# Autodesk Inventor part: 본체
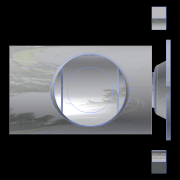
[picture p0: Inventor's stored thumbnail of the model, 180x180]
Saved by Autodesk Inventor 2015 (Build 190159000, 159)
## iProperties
Created: 2017-10
Part Number: 본체
Material: 알루미늄 6061
Document SubType Name: Modeling
Designer: Administrator
Density: 2.7 g/cm^3
Appearance: 알루미늄 - 평지
Mass: 787.092 g
Surface Area: 684.645 cm^2
Volume: 291.516 cm^3
Author: Administrator
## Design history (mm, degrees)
sketch "스케치2"
  geometry: C1 r 31 at (0, 0); 1 further point
  constraints: 1 centre point, 1 coincident
  dimensions: "d1" = 62 diameter of C1
extrude "돌출1" new body sketch "스케치2" stored distance "d2" = 112; taper "d3" = 0 deg
node "작업 평면5"
sketch "스케치5"
  geometry: 1 further point
hole "구멍1" sketch "스케치5" at (0, 0) diameter "d12" = 40.376; stored, may be unused: countersink angle "d16" = 90 deg, drill point angle "d18" = 0 deg; dims "d13" = 84, "d14" = 4, "d15" = 2, "d17" = 9
sketch "스케치6"
  geometry: L1 (20.188, 47)-(-20.188, 47) reference; L2 (31, -56)-(31, 56) reference; L3 (-31, -56)-(-31, 56) reference; L4 (31, 56)-(-31, 56) reference; L5 (20.188, 47)-(24, 47); L6 (24, 47)-(24, 44); L7 (24, 44)-(20, 44); L8 (20, 44)-(20, 35); L9 (20, 35)-(17.5, 35); L10 (17.5, 35)-(17.5, 31.7); L11 (17.5, 31.7)-(18.5, 31.7); L12 (18.5, 31.7)-(18.5, 30); L13 (18.5, 30)-(17.5, 30); L14 (17.5, 30)-(17.5, 19); L15 (17.5, 19)-(26, 19); L16 (26, 19)-(20, 19); L17 (0, 0)-(0, 56); L18 (26, 19)-(26, -19); L19 (26, -19)-(17.5, -19); L20 (17.5, -19)-(17.5, -30); L21 (17.5, -30)-(16.5, -30); L22 (16.5, -30)-(16.5, -35); L23 (16.5, -35)-(10, -35); L24 (10, -35)-(10, -37.7); L25 (10, -37.7)-(12.5, -37.7); L26 (12.5, -37.7)-(12.5, -45); L27 (12.5, -45)-(16.5, -45); L28 (16.5, -45)-(22, -56); L29 (0, 0)-(0, -56); L30 (22, -56)-(0, -56); L31 (20.188, 47)-(0, 47); L32 (-31, -56)-(31, -56) reference
  constraints: 54 end point, 16 perpendicular, 4 horizontal, 4 point on line, 2 midpoint, 2 vertical, 1 horizontal alignment
  dimensions: "d19" = 48 diameter of L6 L17; "d20" = 3 distance between parallel lines of L7 L5; "d21" = 9 distance between parallel lines of L9 L7; "d22" = 40 diameter of L8 L17; "d23" = 35 diameter of L10 L17; "d24" = 26 distance between parallel lines of L13 L4; "d25" = 37 diameter of L12 L17; "d26" = 1.7 distance between parallel lines of L13 L11; "d27" = 11 distance between parallel lines of L15 L13; "d29" = 52 diameter of L18 L17; "d30" = 38 distance of L15.end L18.end; "d31" = 11 distance between parallel lines of L21 L19; "d32" = 35 diameter of L20 L17; "d33" = 5 distance between parallel lines of L23 L21; "d34" = 33 diameter of L22 L17; "d35" = 20 diameter of L24 L17; "d36" = 2.7 distance between parallel lines of L23 L25; "d37" = 7.3 distance between parallel lines of L27 L25; "d38" = 25 diameter of L26 L17; "d39" = 33 diameter of L27.end L17; "d40" = 44 diameter of L28.end L17
node "작업 평면2"
sketch "스케치7"
  geometry: L1 (31, 56)-(-31, 56) reference; C1 r 25 at (0, 0); 1 further point
  constraints: 1 centre point, 1 coincident
  dimensions: "d58" = 56 distance from line of point (0, 0) L1 (derived); "d59" = 50 diameter of C1
extrude "돌출4" join sketch "스케치7" stored distance "d60" = 3; taper "d61" = 0 deg
fillet "모깎기5" dims "d62" = 3
sketch "스케치8"
  geometry: 1 further point
hole "구멍2" sketch "스케치8" at (0, 0) diameter "d63" = 32; stored, may be unused: countersink angle "d67" = 90 deg, drill point angle "d69" = 0 deg; dims "d64" = 84, "d65" = 4, "d66" = 2, "d68" = 30
chamfer "모따기3" distance "d70" = 1; stored, may be unused: second distance "d71" = 2, angle "d72" = 30 deg
sketch "스케치9" dims "d74" = 41
  geometry: 3 further points
  constraints: 2 vertical alignment, 1 coincident, 2 other
hole "구멍3" sketch "스케치9" at (0, -20.5) diameter "d75" = 2.459; stored, may be unused: countersink angle "d79" = 90 deg, drill point angle "d81" = 118 deg; dims "d76" = 6, "d77" = 4, "d78" = 2, "d80" = 8
node "작업 평면4"
node "작업 평면3"
sketch "스케치11"
  geometry: L1 (0, -25)-(0, 25) reference; L2 (-16, 56)-(-78, 56) reference; 3 further points
  constraints: 1 horizontal alignment, 1 midpoint, 1 other
  dimensions: "d96" = 10 distance of point (-10, 0) point (0, 0)
feature "엠보싱1" sketch "스케치11" dims "d3" = 0, "d97" = 0.5, "d98" = 0
node "작업 평면6"
sketch "스케치12"
  geometry: L1 (47, -58)-(47, 58) reference; L2 (-47, -58)-(47, -58) reference; L3 (47, 58)-(-47, 58) reference; L4 (-47, 58)-(-47, -58) reference; 1 further point
extrude "돌출6" join sketch "스케치12" distance "d100" = 10; taper "d101" = 0 deg
sketch "스케치13"
  geometry: L1 (47, -53)-(-47, -53) reference; L2 (47, -53)-(47, -72.757); L3 (47, -72.757)-(-47, -72.757); L4 (-47, -72.757)-(-47, -53); 1 further point
  constraints: 6 end point, 2 perpendicular, 1 vertical
extrude "돌출7" cut sketch "스케치13" stored distance "d102" = 10; taper "d103" = 0 deg
sketch "스케치14"
  geometry: C1 r 35 at (0, 0); 2 further points
  constraints: 2 coincident, 1 centre point
  dimensions: "d104" = 70 diameter of C1
extrude "돌출8" join sketch "스케치14" distance "d105" = 3; taper "d106" = 0 deg
revolve "회전2" stored, may be unused: angle "d107" = 90 deg
sketch "스케치15"
  geometry: L1 (20, 42)-(-20, 42) reference; L2 (-20, 50)-(20, 50) reference; L3 (-20, -50)-(20, -50) reference; L4 (20, -42)-(-20, -42) reference; A1 r 4 centre (20, 46) between (20, 42) and (20, 50) reference; A2 r 4 centre (-20, 46) between (-20, 50) and (-20, 42) reference; A3 r 4 centre (20, -46) between (20, -50) and (20, -42) reference; A4 r 4 centre (-20, -46) between (-20, -42) and (-20, -50) reference; 1 further point
extrude "돌출9" cut sketch "스케치15" stored distance "d108" = 3; taper "d109" = 0 deg
fillet "모깎기7" dims "d110" = 3
fillet "모깎기8" dims "d111" = 0.3
chamfer "모따기5" distance "d112" = 0.7; stored, may be unused: second distance "d113" = 2, angle "d114" = 30 deg
chamfer "모따기6" distance "d115" = 1; stored, may be unused: second distance "d116" = 2, angle "d117" = 30 deg
chamfer "모따기7" distance "d118" = 20; stored, may be unused: second distance "d119" = 2, angle "d120" = 30 deg
node "솔리드1"
pattern_circular "원형 패턴1" dims angle "d83" = 360 deg
other parameters: "d49" = 0.5, "d50" = 2, "d51" = 0, "d57" = -47, "d99" = -13
